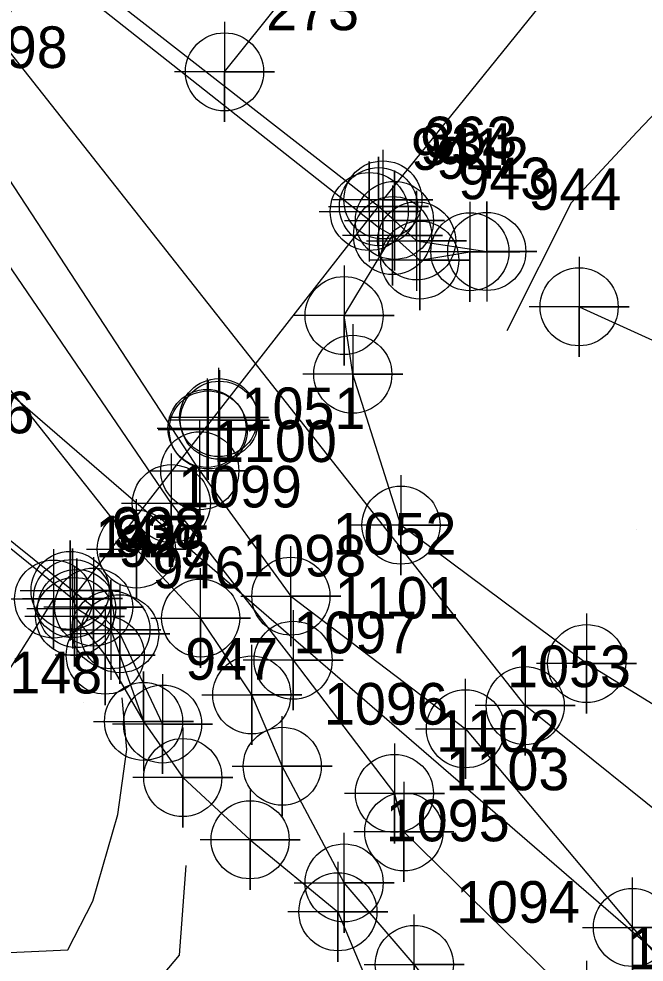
# Model space of a CAD drawing. Extents: x 1497074 to 1501343, y 481943 to 486114.
# Drawn here: x 1498741.6 to 1498779.1, y 484965.4 to 485022 of the extents above; entities that cross this region are included whole.
import ezdxf

# ---------------------------------------------------------------- set-up
doc = ezdxf.new("R2010")
doc.units = 0
for name, color, linetype in [('Exist DTM Breakline', 7, 'Continuous'), ('Exist DTM Breakline Cogo Point CELL', 7, 'Continuous'), ('Exist DTM Breakline Underwater', 7, 'Continuous'), ('Exist DTM Breakline Underwater Cogo Number', 7, 'Continuous'), ('Exist DTM Breakline Underwater Cogo Point CELL', 7, 'Continuous'), ('Exist DTM Crownline', 7, 'Continuous'), ('Exist DTM Crownline Cogo Number', 7, 'Continuous'), ('Exist DTM Crownline Cogo Point CELL', 7, 'Continuous'), ('Exist Hydro Stream or Body of Water', 7, 'Continuous'), ('Exist Hydro Stream or Body of Water Cogo Number', 7, 'Continuous'), ('Exist Hydro Stream or Body of Water Cogo Point CELL', 7, 'Continuous'), ('Exist Roads EOP', 7, 'Continuous'), ('Exist Roads EOP Cogo Number', 7, 'Continuous'), ('Exist Roads EOP Cogo Point CELL', 7, 'Continuous'), ('Exist Structure Major Bridge Seat Cogo Number', 7, 'Continuous'), ('Exist Structure Major Bridge Seat Cogo Point CELL', 7, 'Continuous'), ('Exist Structure Major Bridge WW', 7, 'Continuous'), ('Exist Structure Major Deck Tunnel Box Culvert', 7, 'Continuous'), ('Exist Structure Major Deck Tunnel Box Culvert Cogo Number', 7, 'Continuous'), ('Exist Structure Major Deck Tunnel Box Culvert Cogo Point CELL', 7, 'Continuous'), ('Exist Structure Minor Head and End Wall Cogo Number', 7, 'Continuous'), ('Exist Structure Minor Head and End Wall Cogo Point CELL', 7, 'Continuous'), ('PH Exist DTM Boundary', 7, 'Continuous'), ('PH Exist DTM Breakline', 7, 'Continuous'), ('PH Exist DTM Point', 7, 'Continuous')]:
    doc.layers.add(name, color=color, linetype=linetype)

msp = doc.modelspace()

# ---------------------------------------------------------------- linework, layer by layer
at = {"layer": 'Exist DTM Breakline'}
for points in [[(1498771.972, 484980.758), (1498739.116, 485022.436), (1498734.831, 485026.719), (1498732.74, 485030.214)], [(1498764.124, 485009.903), (1498763.166, 485010.731)], [(1498848.292, 484918.89), (1498845.041, 484921.704), (1498840.429, 484924.269), (1498836.925, 484932.708), (1498831.609, 484940.161), (1498825.714, 484945.619), (1498813.985, 484951.954), (1498810.046, 484953.428), (1498804.816, 484955.732), (1498800.953, 484964.701), (1498787.717, 484975.869), (1498775.661, 484983.284), (1498764.516, 484991.601), (1498761.621, 485000.663), (1498761.098, 485004.192), (1498764.009, 485008.997), (1498765.641, 485007.523), (1498768.65, 485008.021)], [(1498775.209, 485004.717), (1498793.794, 484996.259), (1498808.418, 484984.36), (1498833.912, 484968.522), (1498856.984, 484952.274), (1498870.258, 484939.101), (1498876.949, 484932.871)], [(1498745.045, 484986.591), (1498744.796, 484987.193)], [(1498746.064, 484986.682), (1498747.631, 484985.076), (1498750.201, 484979.653)], [(1498744.924, 484986.112), (1498746.762, 484983.791), (1498749.06, 484979.813), (1498751.417, 484976.439), (1498755.46, 484972.7), (1498760.731, 484968.375), (1498763.327, 484962.192), (1498774.083, 484951.562), (1498777.725, 484947.762), (1498788.851, 484944.25), (1498794.493, 484945.403), (1498805.537, 484938.247), (1498812.462, 484932.808), (1498812.917, 484927.648), (1498823.11, 484919.468), (1498839.025, 484907.273), (1498853.682, 484892.117), (1498858.036, 484879.067)], [(1498800.009, 484958.89), (1498791.246, 484965.262), (1498782.276, 484972.475), (1498771.972, 484980.758)]]:
    msp.add_lwpolyline(points, dxfattribs=at)
at = {"layer": 'Exist DTM Breakline Cogo Point CELL'}
for points in [[(1498764.009, 485011.997), (1498764.009, 485005.997), (1498764.009, 485008.997), (1498767.009, 485008.997), (1498761.009, 485008.997)], [(1498768.65, 485011.021), (1498768.65, 485005.021), (1498768.65, 485008.021), (1498771.65, 485008.021), (1498765.65, 485008.021)], [(1498765.641, 485010.523), (1498765.641, 485004.523), (1498765.641, 485007.523), (1498768.641, 485007.523), (1498762.641, 485007.523)], [(1498775.209, 485007.717), (1498775.209, 485001.717), (1498775.209, 485004.717), (1498778.209, 485004.717), (1498772.209, 485004.717)], [(1498761.098, 485007.192), (1498761.098, 485001.192), (1498761.098, 485004.192), (1498764.098, 485004.192), (1498758.098, 485004.192)], [(1498761.621, 485003.663), (1498761.621, 484997.663), (1498761.621, 485000.663), (1498764.621, 485000.663), (1498758.621, 485000.663)], [(1498753.569, 485001.058), (1498753.569, 484995.058), (1498753.569, 484998.058), (1498756.569, 484998.058), (1498750.569, 484998.058)], [(1498753.612, 485000.902), (1498753.612, 484994.902), (1498753.612, 484997.902), (1498756.612, 484997.902), (1498750.612, 484997.902)], [(1498752.872, 485000.41), (1498752.872, 484994.41), (1498752.872, 484997.41), (1498755.872, 484997.41), (1498749.872, 484997.41)], [(1498752.945, 485000.318), (1498752.945, 484994.318), (1498752.945, 484997.318), (1498755.945, 484997.318), (1498749.945, 484997.318)], [(1498764.516, 484994.601), (1498764.516, 484988.601), (1498764.516, 484991.601), (1498767.516, 484991.601), (1498761.516, 484991.601)], [(1498746.064, 484989.682), (1498746.064, 484983.682), (1498746.064, 484986.682), (1498749.064, 484986.682), (1498743.064, 484986.682)], [(1498744.924, 484989.112), (1498744.924, 484983.112), (1498744.924, 484986.112), (1498747.924, 484986.112), (1498741.924, 484986.112)], [(1498747.631, 484988.076), (1498747.631, 484982.076), (1498747.631, 484985.076), (1498750.631, 484985.076), (1498744.631, 484985.076)], [(1498746.762, 484986.791), (1498746.762, 484980.791), (1498746.762, 484983.791), (1498749.762, 484983.791), (1498743.762, 484983.791)], [(1498775.661, 484986.284), (1498775.661, 484980.284), (1498775.661, 484983.284), (1498778.661, 484983.284), (1498772.661, 484983.284)], [(1498771.972, 484983.758), (1498771.972, 484977.758), (1498771.972, 484980.758), (1498774.972, 484980.758), (1498768.972, 484980.758)], [(1498750.201, 484982.653), (1498750.201, 484976.653), (1498750.201, 484979.653), (1498753.201, 484979.653), (1498747.201, 484979.653)], [(1498751.417, 484979.439), (1498751.417, 484973.439), (1498751.417, 484976.439), (1498754.417, 484976.439), (1498748.417, 484976.439)], [(1498755.46, 484975.7), (1498755.46, 484969.7), (1498755.46, 484972.7), (1498758.46, 484972.7), (1498752.46, 484972.7)], [(1498760.731, 484971.375), (1498760.731, 484965.375), (1498760.731, 484968.375), (1498763.731, 484968.375), (1498757.731, 484968.375)]]:
    msp.add_lwpolyline(points, dxfattribs=at)
for centre in [(1498764.009, 485008.997), (1498768.65, 485008.021), (1498765.641, 485007.523), (1498775.209, 485004.717), (1498761.098, 485004.192), (1498761.621, 485000.663), (1498753.569, 484998.058), (1498753.612, 484997.902), (1498752.872, 484997.41), (1498752.945, 484997.318), (1498764.516, 484991.601), (1498746.064, 484986.682), (1498744.924, 484986.112), (1498747.631, 484985.076), (1498746.762, 484983.791), (1498775.661, 484983.284), (1498771.972, 484980.758), (1498750.201, 484979.653), (1498751.417, 484976.439), (1498755.46, 484972.7), (1498760.731, 484968.375)]:
    msp.add_circle(centre, 2.344, dxfattribs=at)
at = {"layer": 'Exist DTM Breakline Underwater'}
for points in [[(1498727.595, 485023.459), (1498734.573, 485016.558), (1498750.727, 484992.894)], [(1498750.727, 484992.894), (1498758.041, 484983.484), (1498764.121, 484975.484), (1498764.687, 484973.176), (1498775.645, 484962.423), (1498785.172, 484949.251), (1498793.421, 484948.786), (1498808.563, 484943.259), (1498823.454, 484934.258), (1498824.107, 484928.786), (1498829.621, 484922.457), (1498831.917, 484922.463), (1498835.816, 484919.773), (1498853.921, 484901.696), (1498865.619, 484885.93), (1498869.471, 484876.852)]]:
    msp.add_lwpolyline(points, dxfattribs=at)
at = {"layer": 'Exist DTM Breakline Underwater Cogo Point CELL'}
for points in [[(1498750.727, 484995.894), (1498750.727, 484989.894), (1498750.727, 484992.894), (1498753.727, 484992.894), (1498747.727, 484992.894)], [(1498758.041, 484986.484), (1498758.041, 484980.484), (1498758.041, 484983.484), (1498761.041, 484983.484), (1498755.041, 484983.484)], [(1498764.121, 484978.484), (1498764.121, 484972.484), (1498764.121, 484975.484), (1498767.121, 484975.484), (1498761.121, 484975.484)], [(1498764.687, 484976.176), (1498764.687, 484970.176), (1498764.687, 484973.176), (1498767.687, 484973.176), (1498761.687, 484973.176)], [(1498775.645, 484965.423), (1498775.645, 484959.423), (1498775.645, 484962.423), (1498778.645, 484962.423), (1498772.645, 484962.423)]]:
    msp.add_lwpolyline(points, dxfattribs=at)
for centre in [(1498750.727, 484992.894), (1498758.041, 484983.484), (1498764.121, 484975.484), (1498764.687, 484973.176)]:
    msp.add_circle(centre, 2.344, dxfattribs=at)
at = {"layer": 'Exist DTM Crownline'}
msp.add_lwpolyline([(1498753.92, 485018.828), (1498767.966, 485036.345), (1498784.408, 485057.611), (1498813.329, 485094.71), (1498845.111, 485135.393), (1498876.051, 485175.216), (1498907.703, 485215.72), (1498939.873, 485257.15), (1498970.73, 485296.323), (1499001.597, 485335.499), (1499032.553, 485374.361), (1499053.876, 485400.499), (1499073.907, 485423.482), (1499090.486, 485441.639), (1499112.369, 485464.569), (1499148.431, 485501.473), (1499184.544, 485537.766), (1499215.926, 485569.247), (1499248.506, 485602.515), (1499285.018, 485638.963), (1499320.994, 485674.798), (1499344.91, 485698.567), (1499374.037, 485727.35), (1499398.206, 485750.958)], dxfattribs=at)
at = {"layer": 'Exist DTM Crownline Cogo Point CELL'}
msp.add_lwpolyline([(1498753.92, 485021.828), (1498753.92, 485015.828), (1498753.92, 485018.828), (1498756.92, 485018.828), (1498750.92, 485018.828)], dxfattribs=at)
msp.add_circle((1498753.92, 485018.828), 2.344, dxfattribs=at)
at = {"layer": 'Exist Hydro Stream or Body of Water'}
for points in [[(1498752.438, 484994.867), (1498736.246, 485019.606), (1498732.838, 485025.301), (1498730.329, 485028.017)], [(1498748.628, 484990.164), (1498730.808, 485012.654), (1498726.932, 485017.567), (1498725.203, 485021.048)], [(1498752.438, 484994.867), (1498757.907, 484987.334), (1498768.387, 484979.368), (1498778.414, 484967.435), (1498786.595, 484957.957), (1498794.74, 484956.309), (1498800.316, 484956.391), (1498808.697, 484950.708), (1498819.061, 484944.957), (1498828.441, 484936.124), (1498833.877, 484929.917), (1498837.647, 484922.312), (1498844.307, 484916.695), (1498846.681, 484914.59)], [(1498863.2, 484880.012), (1498857.14, 484893.93), (1498847.661, 484902.723), (1498837.7, 484911.613), (1498823.676, 484922.049), (1498815.699, 484933.385), (1498806.396, 484941.639), (1498794.463, 484948.152), (1498786.694, 484947.137), (1498778.282, 484951.134), (1498774.326, 484954.144), (1498765.315, 484965.218), (1498761.102, 484970.11), (1498757.389, 484977.117), (1498755.556, 484981.402), (1498752.488, 484986.02), (1498748.628, 484990.164)]]:
    msp.add_lwpolyline(points, dxfattribs=at)
at = {"layer": 'Exist Hydro Stream or Body of Water Cogo Point CELL'}
for points in [[(1498749.438, 484994.867), (1498755.438, 484994.867), (1498752.438, 484994.867), (1498752.438, 484991.867), (1498752.438, 484997.867)], [(1498745.628, 484990.164), (1498751.628, 484990.164), (1498748.628, 484990.164), (1498748.628, 484987.164), (1498748.628, 484993.164)], [(1498754.907, 484987.334), (1498760.907, 484987.334), (1498757.907, 484987.334), (1498757.907, 484984.334), (1498757.907, 484990.334)], [(1498749.488, 484986.02), (1498755.488, 484986.02), (1498752.488, 484986.02), (1498752.488, 484983.02), (1498752.488, 484989.02)], [(1498752.556, 484981.402), (1498758.556, 484981.402), (1498755.556, 484981.402), (1498755.556, 484978.402), (1498755.556, 484984.402)], [(1498765.387, 484979.368), (1498771.387, 484979.368), (1498768.387, 484979.368), (1498768.387, 484976.368), (1498768.387, 484982.368)], [(1498754.389, 484977.117), (1498760.389, 484977.117), (1498757.389, 484977.117), (1498757.389, 484974.117), (1498757.389, 484980.117)], [(1498758.102, 484970.11), (1498764.102, 484970.11), (1498761.102, 484970.11), (1498761.102, 484967.11), (1498761.102, 484973.11)], [(1498775.414, 484967.435), (1498781.414, 484967.435), (1498778.414, 484967.435), (1498778.414, 484964.435), (1498778.414, 484970.435)], [(1498762.315, 484965.218), (1498768.315, 484965.218), (1498765.315, 484965.218), (1498765.315, 484962.218), (1498765.315, 484968.218)]]:
    msp.add_lwpolyline(points, dxfattribs=at)
for centre in [(1498752.438, 484994.867), (1498748.628, 484990.164), (1498757.907, 484987.334), (1498752.488, 484986.02), (1498755.556, 484981.402), (1498768.387, 484979.368), (1498757.389, 484977.117), (1498761.102, 484970.11), (1498778.414, 484967.435), (1498765.315, 484965.218)]:
    msp.add_circle(centre, 2.344, dxfattribs=at)
at = {"layer": 'Exist Roads EOP'}
for points in [[(1499157.404, 485492.594), (1499121.256, 485455.441), (1499103.509, 485436.374), (1499090.832, 485422.859), (1499076.185, 485406.524), (1499058.807, 485386.534), (1499043.509, 485368.326), (1499011.402, 485327.873), (1498980.601, 485289.07), (1498949.575, 485249.28), (1498917.764, 485208.174), (1498886.394, 485167.841), (1498854.946, 485127.373), (1498823.539, 485086.976), (1498794.252, 485049.828), (1498777.788, 485028.941), (1498763.431, 485011.135)], [(1498743.659, 484987.162), (1498738.498, 484978.991), (1498725.098, 484961.132), (1498703.009, 484933.772), (1498691.756, 484919.758), (1498658.665, 484879.665), (1498641.021, 484858.797), (1498630.746, 484847.819), (1498623.098, 484838.96), (1498603.65, 484817.74), (1498589.503, 484802.3), (1498575.555, 484786.504), (1498555.482, 484765.723), (1498538.212, 484747.039), (1498518.626, 484726.675), (1498501.899, 484709.282), (1498485.079, 484691.463), (1498474.433, 484677.642), (1498470.633, 484672.31)]]:
    msp.add_lwpolyline(points, dxfattribs=at)
at = {"layer": 'Exist Roads EOP Cogo Point CELL'}
for points in [[(1498763.431, 485014.135), (1498763.431, 485008.135), (1498763.431, 485011.135), (1498766.431, 485011.135), (1498760.431, 485011.135)], [(1498743.659, 484990.162), (1498743.659, 484984.162), (1498743.659, 484987.162), (1498746.659, 484987.162), (1498740.659, 484987.162)]]:
    msp.add_lwpolyline(points, dxfattribs=at)
for centre in [(1498763.431, 485011.135), (1498743.659, 484987.162)]:
    msp.add_circle(centre, 2.344, dxfattribs=at)
at = {"layer": 'Exist Structure Major Bridge Seat Cogo Point CELL'}
for points in [[(1498759.612, 485010.44), (1498765.612, 485010.44), (1498762.612, 485010.44), (1498762.612, 485013.44), (1498762.612, 485007.44)], [(1498741.652, 484987.676), (1498747.652, 484987.676), (1498744.652, 484987.676), (1498744.652, 484990.676), (1498744.652, 484984.676)]]:
    msp.add_lwpolyline(points, dxfattribs=at)
for centre in [(1498762.612, 485010.44), (1498744.652, 484987.676)]:
    msp.add_circle(centre, 2.344, dxfattribs=at)
at = {"layer": 'Exist Structure Major Bridge WW'}
for points in [[(1498764.124, 485009.903), (1498765.455, 485008.676), (1498769.665, 485008.039)], [(1498745.045, 484986.591), (1498747.099, 484985.312), (1498749.06, 484979.813)]]:
    msp.add_lwpolyline(points, dxfattribs=at)
at = {"layer": 'Exist Structure Major Deck Tunnel Box Culvert'}
msp.add_lwpolyline([(1498763.166, 485010.731), (1498743.803, 485025.883), (1498725.437, 485002.865), (1498744.796, 484987.193), (1498763.166, 485010.731)], dxfattribs=at)
at = {"layer": 'Exist Structure Major Deck Tunnel Box Culvert Cogo Point CELL'}
for points in [[(1498760.166, 485010.731), (1498766.166, 485010.731), (1498763.166, 485010.731), (1498763.166, 485013.731), (1498763.166, 485007.731)], [(1498741.796, 484987.193), (1498747.796, 484987.193), (1498744.796, 484987.193), (1498744.796, 484990.193), (1498744.796, 484984.193)]]:
    msp.add_lwpolyline(points, dxfattribs=at)
for centre in [(1498763.166, 485010.731), (1498744.796, 484987.193)]:
    msp.add_circle(centre, 2.344, dxfattribs=at)
at = {"layer": 'Exist Structure Minor Head and End Wall Cogo Point CELL'}
for points in [[(1498761.124, 485009.903), (1498767.124, 485009.903), (1498764.124, 485009.903), (1498764.124, 485012.903), (1498764.124, 485006.903)], [(1498762.455, 485008.676), (1498768.455, 485008.676), (1498765.455, 485008.676), (1498765.455, 485011.676), (1498765.455, 485005.676)], [(1498766.665, 485008.039), (1498772.665, 485008.039), (1498769.665, 485008.039), (1498769.665, 485011.039), (1498769.665, 485005.039)], [(1498742.045, 484986.591), (1498748.045, 484986.591), (1498745.045, 484986.591), (1498745.045, 484989.591), (1498745.045, 484983.591)], [(1498744.099, 484985.312), (1498750.099, 484985.312), (1498747.099, 484985.312), (1498747.099, 484988.312), (1498747.099, 484982.312)], [(1498746.06, 484979.813), (1498752.06, 484979.813), (1498749.06, 484979.813), (1498749.06, 484982.813), (1498749.06, 484976.813)]]:
    msp.add_lwpolyline(points, dxfattribs=at)
for centre in [(1498764.124, 485009.903), (1498765.455, 485008.676), (1498769.665, 485008.039), (1498745.045, 484986.591), (1498747.099, 484985.312), (1498749.06, 484979.813)]:
    msp.add_circle(centre, 2.344, dxfattribs=at)
at = {"layer": 'PH Exist DTM Boundary'}
for points in [[(1498924.229, 484841.058), (1498545.187, 485168.899), (1498846.505, 485569.157), (1499227.591, 485244.031)], [(1498186.432, 484771.69), (1498560.82, 484438.227), (1498782.888, 484653.307), (1498924.229, 484841.058), (1498545.187, 485168.899), (1498406.944, 484985.263)]]:
    msp.add_lwpolyline(points, close=True, dxfattribs=at)
at = {"layer": 'PH Exist DTM Breakline'}
for points in [[(1498805.951, 485054.254), (1498804.693, 485050.382), (1498798.609, 485040.733), (1498793.075, 485027.156), (1498789.795, 485024.412), (1498783.947, 485020.733), (1498778.69, 485015.234), (1498774.736, 485010.957), (1498770.868, 485003.271)], [(1498764.009, 485008.997), (1498763.173, 485009.481), (1498743.024, 485025.393), (1498742.708, 485026.892)], [(1498721.307, 485006.558), (1498746.064, 484986.682)], [(1498706.548, 484921.991), (1498706.128, 484926.578), (1498707.646, 484931.296), (1498711.686, 484935.671), (1498715.529, 484941.782), (1498720.924, 484949.822), (1498726.19, 484955.716), (1498730.854, 484960.758), (1498734.775, 484964.844), (1498739.701, 484965.861), (1498744.506, 484966.086), (1498746.012, 484969.019), (1498747.507, 484974.223), (1498748.062, 484978.132), (1498747.785, 484981.236)], [(1498751.598, 484971.154), (1498751.208, 484965.778), (1498747.455, 484961.326), (1498742.587, 484957.633), (1498737.065, 484953.436), (1498732.962, 484949.658), (1498728.691, 484945.192), (1498724.39, 484940.651), (1498721.284, 484935.935), (1498719.744, 484930.434), (1498720.937, 484925.454), (1498723.546, 484921.955)]]:
    msp.add_lwpolyline(points, dxfattribs=at)
at = {"layer": 'PH Exist DTM Point'}
for p, q in [((1498778.661, 484991.363), (1498778.661, 484991.363)), ((1498745.428, 484980.954), (1498745.428, 484980.954))]:
    msp.add_line(p, q, dxfattribs=at)

# ---------------------------------------------------------------- texts
at = {"layer": 'Exist DTM Breakline Underwater Cogo Number'}
for s, p in [('1198', (1498737.073, 485019.058)), ('1100', (1498753.227, 484995.394)), ('1101', (1498760.541, 484985.984)), ('1102', (1498766.621, 484977.984)), ('1103', (1498767.187, 484975.676)), ('1104', (1498778.145, 484964.923))]:
    msp.add_text(s, height=2.5, dxfattribs=at).set_placement(p)
at = {"layer": 'Exist DTM Crownline Cogo Number'}
for s, p in [('273', (1498756.42, 485021.328)), ('146', (1498736.932, 484997.116))]:
    msp.add_text(s, height=2.5, dxfattribs=at).set_placement(p)
at = {"layer": 'Exist Hydro Stream or Body of Water Cogo Number'}
for s, p in [('1051', (1498754.938, 484997.367)), ('1099', (1498751.128, 484992.664)), ('1052', (1498760.407, 484989.834)), ('1098', (1498754.988, 484988.52)), ('1097', (1498758.056, 484983.902)), ('1053', (1498770.887, 484981.868)), ('1096', (1498759.889, 484979.617)), ('1095', (1498763.602, 484972.61)), ('1094', (1498767.815, 484967.718))]:
    msp.add_text(s, height=2.5, dxfattribs=at).set_placement(p)
at = {"layer": 'Exist Roads EOP Cogo Number'}
for s, p in [('363', (1498765.931, 485013.635)), ('147', (1498746.159, 484989.662)), ('148', (1498740.998, 484981.491))]:
    msp.add_text(s, height=2.5, dxfattribs=at).set_placement(p)
at = {"layer": 'Exist Structure Major Bridge Seat Cogo Number'}
for s, p in [('941', (1498765.112, 485012.94)), ('938', (1498747.152, 484990.176))]:
    msp.add_text(s, height=2.5, dxfattribs=at).set_placement(p)
at = {"layer": 'Exist Structure Major Deck Tunnel Box Culvert Cogo Number'}
for s, p in [('934', (1498765.666, 485013.231)), ('937', (1498747.296, 484989.693))]:
    msp.add_text(s, height=2.5, dxfattribs=at).set_placement(p)
at = {"layer": 'Exist Structure Minor Head and End Wall Cogo Number'}
for s, p in [('942', (1498766.624, 485012.403)), ('943', (1498767.955, 485011.176)), ('944', (1498772.165, 485010.539)), ('945', (1498747.545, 484989.091)), ('946', (1498749.599, 484987.812)), ('947', (1498751.56, 484982.313))]:
    msp.add_text(s, height=2.5, dxfattribs=at).set_placement(p)

doc.saveas('drawing.dxf')
